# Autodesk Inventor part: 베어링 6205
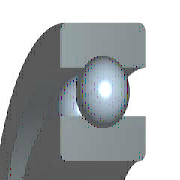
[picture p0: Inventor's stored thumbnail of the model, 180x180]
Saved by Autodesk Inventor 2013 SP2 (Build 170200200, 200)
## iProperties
Created: 2009-02
Part Number: 베어링 6205
Material: 강, 연강
Description: 깊은 그루브 볼 베어링
Document SubType Name: Modeling
Standard: KS B 2023
Designer: SeoGD™[esajin.kr]
Standards Organization: KS
Language: ko-KR
Size Designation: 6205 - 25 x 52 x 15
Categories: <MemberInstance><Categories><Category DisplayName="샤프트 부품" InternalName="7f7aeb1f-a693-4053-b835-cee3144e0d98" Mnemonic="SHFT"><Category DisplayName="베어링" Inter
Density: 7.86 g/cm^3
Mass: 129.543 g
Surface Area: 107.326 cm^2
Volume: 16.4813 cm^3
IsCustomPart: 1
Author: SeoGD™[esajin.kr]
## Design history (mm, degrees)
sketch "스케치" dims "d0" = 7.02 (= -0.26 x WD + 0.26 x BD)
  geometry: L1 (3.99, 19.25)-(11.01, 19.25); L2 (7.5, 19.25)-(7.5, 15.74); L3 (7.5, 19.25)-(7.5, 22.76); L4 (4.892, 16.901)-(0, 16.901); L5 (0, 12.5)-(15, 12.5); L6 (4.892, 21.599)-(0, 21.599); L7 (0, 26)-(15, 26); L8 (15, 12.5)-(15, 16.901); L9 (10.108, 16.901)-(15, 16.901); L10 (10.108, 21.599)-(15, 21.599); L11 (15, 26)-(15, 21.599); L12 (-1.4, 0)-(8.4, 0) reference; L13 (0, -0.3)-(0, 5.3) reference
  constraints: 22 end point, 4 point on line, 2 collinear, 2 perpendicular, 2 symmetric about line, 1 midpoint, 1 parallel, 14 other
  dimensions: "d9" = 25 diameter of L5 L12 (= WD); "d11" = 52 diameter of L7 L12 (= BD); "d12" = 15 distance between parallel lines of L8 L13 (= KB); "d13" = 33.802 diameter of L9 L12 (= 0.326 x BD + 0.674 x WD)
revolve "본체" stored, may be unused: angle "d6" = 90 deg
revolve "볼" stored, may be unused: angle "d7" = 90 deg
pattern_circular "IDS_ARRAYBALL[SIMPL:T]" dims angle "d3" = 360 deg
body "Solid1"
fillet "모깎기1" dims "d1" = 1 (= KRS)
other parameters: "WD" = 25 [user parameter; used in 5 equation terms], "BD" = 52 [user parameter; used in 5 equation terms], "KB" = 15 [user parameter; used in 1 equation term], "KRS" = 1 [user parameter; used in 1 equation term], "d4" = 0, "d5" = 0, "d8" = 0, "d14" = 0, "d15" = 0, "BBA" = 0 [user parameter], "BC0" = 7800000 [user parameter], "BC" = 1.4e+07 [user parameter], "BR" = 26 (= 0.5 x BD) [user parameter], "WR" = 12.5 (= 0.5 x WD) [user parameter]
